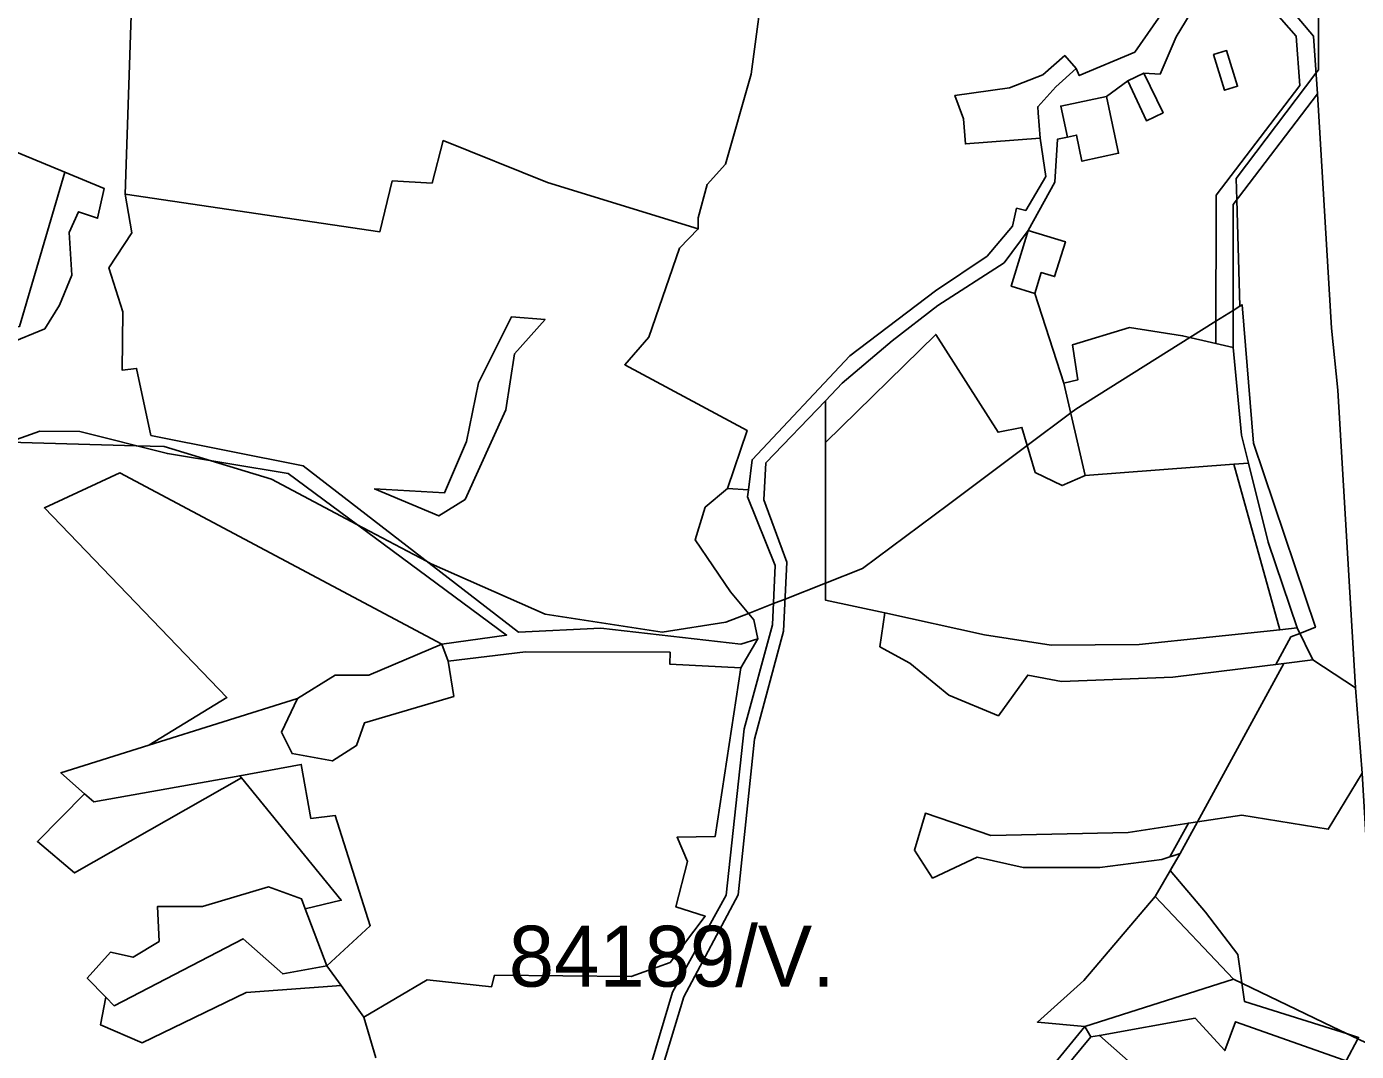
# Model space of a CAD drawing. Extents: x -477304 to -465429, y -1159113 to -1149210.
# Drawn here: x -474893.9 to -474566.3, y -1157226 to -1156973.5 of the extents above; entities that cross this region are included whole.
import ezdxf

# ---------------------------------------------------------------- set-up
doc = ezdxf.new("R2010")
doc.units = 0
for name, color, linetype in [('BPEJ_s', 7, 'Continuous'), ('ostatni_s', 7, 'Continuous'), ('PUPFL_s', 7, 'Continuous'), ('sad_s', 7, 'Continuous'), ('trav_porost_s', 7, 'Continuous'), ('zahrada_s', 7, 'Continuous')]:
    doc.layers.add(name, color=color, linetype=linetype)

msp = doc.modelspace()

# ---------------------------------------------------------------- linework, layer by layer
at = {"layer": 'BPEJ_s'}
for points in [[(-474910.48, -1156725.34), (-474833.78, -1156765.24), (-474818.36, -1156773.73), (-474815.98, -1156775.04), (-474748.53, -1156812.18), (-474688.56, -1156846.68), (-474662.99, -1156859.58), (-474598.28, -1156941.38), (-474597.89, -1156941.87), (-474595.22, -1156945.08), (-474575.63, -1156968.65), (-474575.63, -1156984.14), (-474576.28, -1156985), (-474595.92, -1157010.92), (-474595.77, -1157016.21), (-474595.07, -1157042.42), (-474594.48, -1157042.05), (-474591.67, -1157076.15), (-474576.43, -1157121.49), (-474580.25, -1157123.01), (-474582.45, -1157123.89)], [(-474575.63, -1156968.65), (-474575.63, -1156984.14), (-474576.28, -1156985), (-474595.92, -1157010.92), (-474595.77, -1157016.21), (-474595.07, -1157042.42), (-474596.66, -1157043.42), (-474600.95, -1157046.11), (-474607.31, -1157050.1), (-474635.4, -1157067.73), (-474636.7, -1157068.7), (-474647.39, -1157076.7), (-474666.82, -1157091.23), (-474687.96, -1157107.04), (-474697.12, -1157110.64), (-474707.06, -1157114.55), (-474709.92, -1157115.67), (-474716.07, -1157118.09), (-474721.66, -1157120.28), (-474737.3, -1157122.69), (-474740.55, -1157122.19), (-474766.19, -1157118.28), (-474794.27, -1157105.84), (-474795.36, -1157105.26), (-474812.52, -1157096.15), (-474833.58, -1157084.98), (-474848.45, -1157080.47), (-474860.06, -1157076.96), (-474866.9, -1157076.77), (-474898.2, -1157075.9)], [(-474898.2, -1157075.9), (-474866.9, -1157076.77), (-474860.06, -1157076.96), (-474848.45, -1157080.47), (-474833.58, -1157084.98), (-474812.52, -1157096.15), (-474795.36, -1157105.26), (-474794.27, -1157105.84), (-474766.19, -1157118.28), (-474740.55, -1157122.19), (-474737.3, -1157122.69), (-474721.66, -1157120.28), (-474716.07, -1157118.09), (-474709.92, -1157115.67), (-474707.06, -1157114.55), (-474697.12, -1157110.64), (-474687.96, -1157107.04), (-474666.82, -1157091.23), (-474647.39, -1157076.7), (-474636.7, -1157068.7), (-474635.4, -1157067.73), (-474607.31, -1157050.1), (-474600.95, -1157046.11), (-474596.66, -1157043.42), (-474595.07, -1157042.42), (-474594.48, -1157042.05), (-474591.67, -1157076.15), (-474576.43, -1157121.49), (-474580.25, -1157123.01), (-474582.45, -1157123.89), (-474586.17, -1157130.66), (-474584.16, -1157130.41), (-474605.49, -1157169.45), (-474607.69, -1157169.78), (-474612.24, -1157178.05), (-474609.75, -1157177.25), (-474612.17, -1157181.44), (-474603.51, -1157191.69), (-474595.49, -1157202.12), (-474593.88, -1157213.76), (-474568.54, -1157221.72), (-474565.8, -1157222.58)], [(-474582.45, -1157123.89), (-474586.17, -1157130.66), (-474584.16, -1157130.41), (-474605.49, -1157169.45), (-474607.69, -1157169.78), (-474612.24, -1157178.05), (-474609.75, -1157177.25), (-474612.17, -1157181.44), (-474603.51, -1157191.69), (-474595.49, -1157202.12), (-474593.88, -1157213.76), (-474568.54, -1157221.72), (-474565.8, -1157222.58), (-474565.99, -1157222.94), (-474568.82, -1157228.32)], [(-474565.99, -1157222.94), (-474568.82, -1157228.32)]]:
    msp.add_lwpolyline(points, dxfattribs=at)
at = {"layer": 'ostatni_s'}
for points in [[(-474559.69, -1156837.53), (-474589.27, -1156880.49), (-474593.11, -1156932.76), (-474596.49, -1156952.51), (-474598.57, -1156955.93), (-474610.7, -1156975.97), (-474614.68, -1156985.24), (-474618.65, -1156984.99), (-474622.63, -1156986.84), (-474627.92, -1156990.68), (-474639.16, -1156993.09), (-474637.52, -1157000.73), (-474639.94, -1157001.19), (-474640.58, -1157011.8), (-474647.14, -1157023.71), (-474653.09, -1157031.68), (-474669.39, -1157042.24), (-474680.71, -1157050.93), (-474692.97, -1157061.36), (-474697.14, -1157065.72)], [(-474746.21, -1157249.78), (-474734.77, -1157211.44), (-474721.55, -1157187.56), (-474717.1, -1157146.51), (-474710.15, -1157120.87), (-474709.5, -1157106.25), (-474716.28, -1157089.36), (-474716.08, -1157087.65), (-474715.2, -1157080.22), (-474691.14, -1157054.63), (-474669.97, -1157038.63), (-474657.28, -1157030.08), (-474651, -1157022.63), (-474650.04, -1157018.25), (-474647.78, -1157018.79), (-474642.85, -1157010.42), (-474644.21, -1157000.95), (-474644.69, -1156994.73), (-474644.81, -1156993.25), (-474640.37, -1156988.3), (-474635.33, -1156983.82), (-474634.58, -1156985.56), (-474620.91, -1156979.79), (-474599.66, -1156949.17)], [(-474697.14, -1157065.72), (-474711.77, -1157081.02), (-474712.3, -1157090.12), (-474706.6, -1157105.5), (-474707.46, -1157122.5), (-474714.57, -1157149.07), (-474718.64, -1157187.47), (-474731.98, -1157212.54), (-474744.45, -1157253.74)]]:
    msp.add_lwpolyline(points, dxfattribs=at)
for points in [[(-474600.97, -1157051.58), (-474600.88, -1157015.06), (-474580.25, -1156988.01), (-474581.13, -1156975.81), (-474598.57, -1156955.93), (-474596.49, -1156952.51), (-474576.91, -1156975.84), (-474575.93, -1156990.04), (-474596.64, -1157017.35), (-474596.67, -1157052.59)], [(-474651.76, -1156988.61), (-474643.59, -1156985.41), (-474638.18, -1156980.61), (-474635.33, -1156983.82), (-474640.37, -1156988.3), (-474644.81, -1156993.25), (-474644.69, -1156994.73), (-474644.21, -1157000.95), (-474662.62, -1157002.38), (-474663.11, -1156996.19), (-474665.23, -1156990.43)], [(-474601.5, -1156980.39), (-474598.28, -1156979.4), (-474595.58, -1156988.19), (-474598.8, -1156989.18)], [(-474618.06, -1156996.69), (-474622.63, -1156986.84), (-474618.65, -1156984.99), (-474613.96, -1156994.71)], [(-474627.92, -1156990.68), (-474624.91, -1157004.71), (-474633.94, -1157006.65), (-474635.26, -1157000.24), (-474637.52, -1157000.73), (-474639.16, -1156993.09)], [(-474645.54, -1157039.25), (-474651.36, -1157037.47), (-474647.14, -1157023.71), (-474638.02, -1157026.51), (-474640.66, -1157035.1), (-474643.96, -1157034.09)], [(-474596.48, -1157081.33), (-474592.92, -1157081.06), (-474588.03, -1157100.57), (-474580.91, -1157121.68), (-474585.17, -1157122.12)], [(-474584.16, -1157130.41), (-474611.52, -1157133.81), (-474638.93, -1157134.9), (-474647.29, -1157133.3), (-474654.51, -1157143.3), (-474666.69, -1157138.27), (-474676.33, -1157130.37), (-474683.74, -1157126.33), (-474682.5, -1157117.96), (-474657.96, -1157123.35), (-474641.53, -1157125.93), (-474619.82, -1157125.74), (-474585.17, -1157122.12), (-474580.91, -1157121.68), (-474577.01, -1157129.52)], [(-474656.34, -1157172.79), (-474622.58, -1157172.06), (-474605.49, -1157169.45), (-474609.75, -1157177.25), (-474614.24, -1157178.7), (-474629.54, -1157180.69), (-474648.37, -1157180.72), (-474659.7, -1157178.19), (-474670.72, -1157183.31), (-474675.21, -1157176.43), (-474672.48, -1157167.35)]]:
    msp.add_lwpolyline(points, close=True, dxfattribs=at)
at = {"layer": 'PUPFL_s'}
for points in [[(-474564.87, -1157157.45), (-474566.57, -1157136.41), (-474570.88, -1157063.12), (-474572.44, -1157047.84), (-474575.93, -1156990.04), (-474576.91, -1156975.84), (-474596.49, -1156952.51), (-474593.11, -1156932.76), (-474589.27, -1156880.49), (-474559.69, -1156837.53)], [(-474566.5, -1157229.14), (-474596.12, -1157218.7), (-474598.76, -1157225.82), (-474606.02, -1157217.85), (-474629.62, -1157222.07), (-474631.77, -1157222.45), (-474632, -1157222.05), (-474633.21, -1157219.92), (-474596.58, -1157208.26), (-474572.19, -1157219.97), (-474560.83, -1157225.42), (-474520.06, -1157230.66)], [(-474641.34, -1157229.79), (-474633.21, -1157219.92), (-474632, -1157222.05), (-474631.77, -1157222.45), (-474654.35, -1157249.7)]]:
    msp.add_lwpolyline(points, dxfattribs=at)
for points in [[(-474572.44, -1157047.84), (-474570.88, -1157063.12), (-474566.57, -1157136.41), (-474577.01, -1157129.52), (-474580.91, -1157121.68), (-474588.03, -1157100.57), (-474592.92, -1157081.06), (-474594.63, -1157074.21), (-474596.67, -1157052.59), (-474596.64, -1157017.35), (-474575.93, -1156990.04)], [(-474899.13, -1157070.68), (-474916.01, -1157075.74), (-474938.95, -1157077.02), (-474954.17, -1157078.25), (-474987.5, -1157074.55), (-475015.54, -1157060.67), (-474955.56, -1157054.06), (-474895.66, -1157047.4), (-474884.52, -1157009.38), (-474874.79, -1157013.4), (-474876.41, -1157020.73), (-474881.13, -1157019.11), (-474883.41, -1157024.26), (-474882.74, -1157034.73), (-474885.83, -1157042.11), (-474889.45, -1157047.94), (-474898.18, -1157051.61), (-474901.76, -1157056.2), (-474896.84, -1157066.23)], [(-474870.93, -1157083.43), (-474791.58, -1157125.7), (-474809.64, -1157133.34), (-474817.86, -1157133.29), (-474827.16, -1157139.1), (-474863.81, -1157150.57), (-474844.56, -1157138.8), (-474889.52, -1157092.08)], [(-474885.46, -1157157.34), (-474863.81, -1157150.57), (-474827.16, -1157139.1), (-474831.12, -1157147.34), (-474828.52, -1157152.62), (-474818.58, -1157154.46), (-474812.65, -1157150.67), (-474810.67, -1157145.03), (-474788.67, -1157138.53), (-474790.04, -1157129.85), (-474770.97, -1157127.53), (-474735.38, -1157127.68), (-474735.49, -1157130.57), (-474717.93, -1157131.51), (-474724.3, -1157173.08), (-474733.65, -1157173.24), (-474731.13, -1157179.21), (-474733.98, -1157190.4), (-474726.72, -1157192.71), (-474735.37, -1157204.16), (-474744.95, -1157207.61), (-474778.63, -1157207.26), (-474779.36, -1157210.08), (-474795.27, -1157208.41), (-474810.86, -1157217.55), (-474816.41, -1157209.79), (-474819.97, -1157204.97), (-474809.26, -1157195.07), (-474817.86, -1157167.91), (-474823.93, -1157168.6), (-474826.26, -1157155.32), (-474841.42, -1157158.09), (-474877.38, -1157164.49), (-474879.64, -1157162.52)], [(-474790.04, -1157129.85), (-474788.67, -1157138.53), (-474810.67, -1157145.03), (-474812.65, -1157150.67), (-474818.58, -1157154.46), (-474828.52, -1157152.62), (-474831.12, -1157147.34), (-474827.16, -1157139.1), (-474817.86, -1157133.29), (-474809.64, -1157133.34), (-474791.58, -1157125.7)], [(-474584.16, -1157130.41), (-474577.01, -1157129.52), (-474566.57, -1157136.41), (-474564.87, -1157157.45), (-474573.26, -1157171.3), (-474594.56, -1157167.78), (-474605.49, -1157169.45)], [(-474826.26, -1157155.32), (-474823.93, -1157168.6), (-474817.86, -1157167.91), (-474809.26, -1157195.07), (-474819.97, -1157204.97), (-474825.25, -1157190.92), (-474816.38, -1157188.78), (-474840.97, -1157158.64), (-474841.42, -1157158.09)], [(-474560.83, -1157225.42), (-474572.19, -1157219.97), (-474596.58, -1157208.26), (-474615.85, -1157187.83), (-474609.75, -1157177.25), (-474605.49, -1157169.45), (-474594.56, -1157167.78), (-474573.26, -1157171.3), (-474564.87, -1157157.45), (-474561, -1157222.59)], [(-474841.42, -1157158.09), (-474840.97, -1157158.64), (-474882.08, -1157182.04), (-474891.25, -1157174.3), (-474879.64, -1157162.52), (-474877.38, -1157164.49)], [(-474840.56, -1157198.28), (-474872.33, -1157214.78), (-474874.37, -1157212.68), (-474878.97, -1157207.94), (-474873.24, -1157201.61), (-474867.67, -1157202.84), (-474861.27, -1157198.93), (-474861.69, -1157190.35), (-474850.56, -1157190.29), (-474834.35, -1157185.49), (-474826.18, -1157188.45), (-474825.25, -1157190.92), (-474819.97, -1157204.97), (-474830.81, -1157206.94)], [(-474596.58, -1157208.26), (-474633.21, -1157219.92), (-474644.9, -1157218.82), (-474633.44, -1157208.55), (-474615.85, -1157187.83)], [(-474819.97, -1157204.97), (-474816.41, -1157209.79), (-474839.83, -1157211.52), (-474865.42, -1157223.93), (-474875.71, -1157219.47), (-474874.37, -1157212.68), (-474872.33, -1157214.78), (-474840.56, -1157198.28), (-474830.81, -1157206.94)], [(-474585.32, -1157258.29), (-474592.58, -1157249.28), (-474610.48, -1157239.07), (-474629.62, -1157222.07), (-474606.02, -1157217.85), (-474598.76, -1157225.82), (-474596.12, -1157218.7), (-474566.5, -1157229.14), (-474577.17, -1157250.19)]]:
    msp.add_lwpolyline(points, close=True, dxfattribs=at)
at = {"layer": 'sad_s'}
for points in [[(-474622.63, -1156986.84), (-474618.06, -1156996.69), (-474613.96, -1156994.71), (-474618.65, -1156984.99), (-474614.68, -1156985.24), (-474610.7, -1156975.97), (-474598.57, -1156955.93), (-474581.13, -1156975.81), (-474580.25, -1156988.01), (-474600.88, -1157015.06), (-474600.97, -1157051.58), (-474609.13, -1157049.68), (-474622.22, -1157047.6), (-474636.27, -1157051.92), (-474634.94, -1157060.53), (-474638.42, -1157061.35), (-474645.54, -1157039.25), (-474643.96, -1157034.09), (-474640.66, -1157035.1), (-474638.02, -1157026.51), (-474647.14, -1157023.71), (-474640.58, -1157011.8), (-474639.94, -1157001.19), (-474637.52, -1157000.73), (-474635.26, -1157000.24), (-474633.94, -1157006.65), (-474624.91, -1157004.71), (-474627.92, -1156990.68)], [(-474598.8, -1156989.18), (-474595.58, -1156988.19), (-474598.28, -1156979.4), (-474601.5, -1156980.39)]]:
    msp.add_lwpolyline(points, close=True, dxfattribs=at)
at = {"layer": 'trav_porost_s'}
for points in [[(-474773.25, -1156898.86), (-474704.76, -1156928.45), (-474707.42, -1156949.11), (-474711.92, -1156958.64), (-474715.41, -1156985.25), (-474721.76, -1157007.37), (-474726.25, -1157012.44), (-474728.5, -1157020.58), (-474728.44, -1157023.36), (-474765.56, -1157011.88), (-474791.3, -1157001.58), (-474794.01, -1157012.04), (-474803.83, -1157011.5), (-474806.92, -1157024.07), (-474869.63, -1157014.82), (-474866.46, -1156919.14), (-474870.76, -1156899.79), (-474853.14, -1156897.63), (-474831.94, -1156892.27), (-474826.99, -1156891.24), (-474805.27, -1156893.34), (-474778.46, -1156896.61)], [(-474925.65, -1156992.39), (-474884.52, -1157009.38), (-474895.66, -1157047.4), (-474955.56, -1157054.06), (-474953.98, -1157047.3), (-474990.97, -1157041.57), (-475004.98, -1157045.6), (-474997.52, -1157030.58), (-474994.25, -1157023.99), (-474960.47, -1156977.37), (-474958.94, -1156975.27)], [(-474714.76, -1157119.68), (-474713.79, -1157124.35), (-474717.92, -1157125.65), (-474752.48, -1157121.69), (-474772.76, -1157122.74), (-474825.8, -1157081.72), (-474863.3, -1157074.24), (-474866.82, -1157057.71), (-474870.4, -1157058.12), (-474870.2, -1157043.77), (-474873.65, -1157032.91), (-474867.97, -1157024.34), (-474869.63, -1157014.82), (-474806.92, -1157024.07), (-474803.83, -1157011.5), (-474794.01, -1157012.04), (-474791.3, -1157001.58), (-474765.56, -1157011.88), (-474728.44, -1157023.36), (-474733.04, -1157028.11), (-474740.62, -1157050.03), (-474746.55, -1157056.83), (-474716.44, -1157073.01), (-474721.28, -1157087.35), (-474726.76, -1157091.95), (-474729.18, -1157099.93), (-474720.48, -1157112.75)], [(-474680.71, -1157050.93), (-474669.39, -1157042.24), (-474653.09, -1157031.68), (-474647.14, -1157023.71), (-474651.36, -1157037.47), (-474645.54, -1157039.25), (-474638.42, -1157061.35), (-474633.1, -1157084.14), (-474638.77, -1157086.61), (-474645.43, -1157083.35), (-474648.71, -1157072.24), (-474654.58, -1157073.47), (-474669.94, -1157049.33), (-474697.14, -1157075.96), (-474697.14, -1157065.72), (-474692.97, -1157061.36)], [(-474785.9, -1157090.03), (-474792.38, -1157094.06), (-474808.19, -1157087.4), (-474790.93, -1157088.38), (-474785.53, -1157075.75), (-474782.57, -1157061.26), (-474774.47, -1157045.03), (-474766.17, -1157045.68), (-474773.68, -1157054.13), (-474775.83, -1157067.95)], [(-474785.9, -1157090.03), (-474775.83, -1157067.95), (-474773.68, -1157054.13), (-474766.17, -1157045.68), (-474774.47, -1157045.03), (-474782.57, -1157061.26), (-474785.53, -1157075.75), (-474790.93, -1157088.38), (-474808.19, -1157087.4), (-474792.38, -1157094.06)], [(-474654.58, -1157073.47), (-474648.71, -1157072.24), (-474645.43, -1157083.35), (-474638.77, -1157086.61), (-474633.1, -1157084.14), (-474596.48, -1157081.33), (-474585.17, -1157122.12), (-474619.82, -1157125.74), (-474641.53, -1157125.93), (-474657.96, -1157123.35), (-474682.5, -1157117.96), (-474697.12, -1157114.79), (-474697.14, -1157075.96), (-474669.94, -1157049.33)], [(-474604.43, -1157274.23), (-474611.29, -1157273.73), (-474637.99, -1157260.32), (-474654.35, -1157249.7), (-474631.77, -1157222.45), (-474629.62, -1157222.07), (-474610.48, -1157239.07), (-474592.58, -1157249.28), (-474585.32, -1157258.29), (-474591.99, -1157264.92)]]:
    msp.add_lwpolyline(points, close=True, dxfattribs=at)
for points in [[(-474866.46, -1156919.14), (-474869.63, -1157014.82), (-474867.97, -1157024.34), (-474873.65, -1157032.91), (-474870.2, -1157043.77), (-474870.4, -1157058.12), (-474866.82, -1157057.71), (-474863.3, -1157074.24), (-474825.8, -1157081.72), (-474772.76, -1157122.74), (-474752.48, -1157121.69), (-474717.92, -1157125.65), (-474713.79, -1157124.35), (-474717.93, -1157131.51), (-474735.49, -1157130.57), (-474735.38, -1157127.68), (-474770.97, -1157127.53), (-474790.04, -1157129.85), (-474791.58, -1157125.7), (-474775.67, -1157123.44), (-474829.48, -1157083.6), (-474859.22, -1157078.7), (-474880.78, -1157073.27), (-474890.62, -1157073.17), (-474898.68, -1157076.07)], [(-474599.66, -1156949.17), (-474620.91, -1156979.79), (-474634.58, -1156985.56), (-474635.33, -1156983.82), (-474638.18, -1156980.61), (-474643.59, -1156985.41), (-474651.76, -1156988.61), (-474665.23, -1156990.43), (-474663.11, -1156996.19), (-474662.62, -1157002.38), (-474644.21, -1157000.95), (-474642.85, -1157010.42), (-474647.78, -1157018.79), (-474650.04, -1157018.25), (-474651, -1157022.63), (-474657.28, -1157030.08), (-474669.97, -1157038.63), (-474691.14, -1157054.63), (-474715.2, -1157080.22), (-474716.08, -1157087.65), (-474721.28, -1157087.35), (-474716.44, -1157073.01), (-474746.55, -1157056.83), (-474740.62, -1157050.03), (-474733.04, -1157028.11), (-474728.44, -1157023.36), (-474728.5, -1157020.58), (-474726.25, -1157012.44), (-474721.76, -1157007.37), (-474715.41, -1156985.25), (-474711.92, -1156958.64)], [(-474898.18, -1157051.61), (-474889.45, -1157047.94), (-474885.83, -1157042.11), (-474882.74, -1157034.73), (-474883.41, -1157024.26), (-474881.13, -1157019.11), (-474876.41, -1157020.73), (-474874.79, -1157013.4), (-474884.52, -1157009.38), (-474925.65, -1156992.39)], [(-474744.45, -1157253.74), (-474731.98, -1157212.54), (-474718.64, -1157187.47), (-474714.57, -1157149.07), (-474707.46, -1157122.5), (-474706.6, -1157105.5), (-474712.3, -1157090.12), (-474711.77, -1157081.02), (-474697.14, -1157065.72), (-474697.14, -1157075.96), (-474697.12, -1157114.79), (-474682.5, -1157117.96), (-474683.74, -1157126.33), (-474676.33, -1157130.37), (-474666.69, -1157138.27), (-474654.51, -1157143.3), (-474647.29, -1157133.3), (-474638.93, -1157134.9), (-474611.52, -1157133.81), (-474584.16, -1157130.41), (-474605.49, -1157169.45), (-474622.58, -1157172.06), (-474656.34, -1157172.79), (-474672.48, -1157167.35), (-474675.21, -1157176.43), (-474670.72, -1157183.31), (-474659.7, -1157178.19), (-474648.37, -1157180.72), (-474629.54, -1157180.69), (-474614.24, -1157178.7), (-474609.75, -1157177.25), (-474615.85, -1157187.83), (-474633.44, -1157208.55), (-474644.9, -1157218.82), (-474633.21, -1157219.92), (-474641.34, -1157229.79)], [(-474898.68, -1157076.07), (-474890.62, -1157073.17), (-474880.78, -1157073.27), (-474859.22, -1157078.7), (-474829.48, -1157083.6), (-474775.67, -1157123.44), (-474791.58, -1157125.7), (-474870.93, -1157083.43), (-474889.52, -1157092.08), (-474844.56, -1157138.8), (-474863.81, -1157150.57), (-474885.46, -1157157.34), (-474879.64, -1157162.52), (-474891.25, -1157174.3), (-474882.08, -1157182.04), (-474840.97, -1157158.64), (-474816.38, -1157188.78), (-474825.25, -1157190.92), (-474826.18, -1157188.45), (-474834.35, -1157185.49), (-474850.56, -1157190.29), (-474861.69, -1157190.35), (-474861.27, -1157198.93), (-474867.67, -1157202.84), (-474873.24, -1157201.61), (-474878.97, -1157207.94), (-474874.37, -1157212.68), (-474875.71, -1157219.47), (-474865.42, -1157223.93), (-474839.83, -1157211.52), (-474816.41, -1157209.79), (-474810.86, -1157217.55), (-474807.85, -1157227.61)], [(-474807.85, -1157227.61), (-474810.86, -1157217.55), (-474795.27, -1157208.41), (-474779.36, -1157210.08), (-474778.63, -1157207.26), (-474744.95, -1157207.61), (-474735.37, -1157204.16), (-474726.72, -1157192.71), (-474733.98, -1157190.4), (-474731.13, -1157179.21), (-474733.65, -1157173.24), (-474724.3, -1157173.08), (-474717.93, -1157131.51), (-474713.79, -1157124.35), (-474714.76, -1157119.68), (-474720.48, -1157112.75), (-474729.18, -1157099.93), (-474726.76, -1157091.95), (-474721.28, -1157087.35), (-474716.08, -1157087.65), (-474716.28, -1157089.36), (-474709.5, -1157106.25), (-474710.15, -1157120.87), (-474717.1, -1157146.51), (-474721.55, -1157187.56), (-474734.77, -1157211.44), (-474746.21, -1157249.78)]]:
    msp.add_lwpolyline(points, dxfattribs=at)
at = {"layer": 'zahrada_s'}
msp.add_lwpolyline([(-474600.97, -1157051.58), (-474596.67, -1157052.59), (-474594.63, -1157074.21), (-474592.92, -1157081.06), (-474596.48, -1157081.33), (-474633.1, -1157084.14), (-474638.42, -1157061.35), (-474634.94, -1157060.53), (-474636.27, -1157051.92), (-474622.22, -1157047.6), (-474609.13, -1157049.68)], close=True, dxfattribs=at)

# ---------------------------------------------------------------- texts
at = {"layer": 'BPEJ_s'}
msp.add_text('84189/V.', height=15, dxfattribs=at).set_placement((-474775.12, -1157210.06))

doc.saveas('drawing.dxf')
